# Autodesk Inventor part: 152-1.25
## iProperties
Created: 2007-06
Part Number: 152-1.25
Document SubType Name: Modeling
Designer: btaylor
Density: 1 g/cm^3
Author: btaylor
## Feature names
1. Sweep1
2. Extrusion1
3. Extrusion2
4. Fillet1
5. Fillet2
6. Extrusion3
7. Sweep3
8. Fillet3
9. Chamfer2
10. Fillet4
11. Chamfer3
12. Fillet5
13. Fillet6
